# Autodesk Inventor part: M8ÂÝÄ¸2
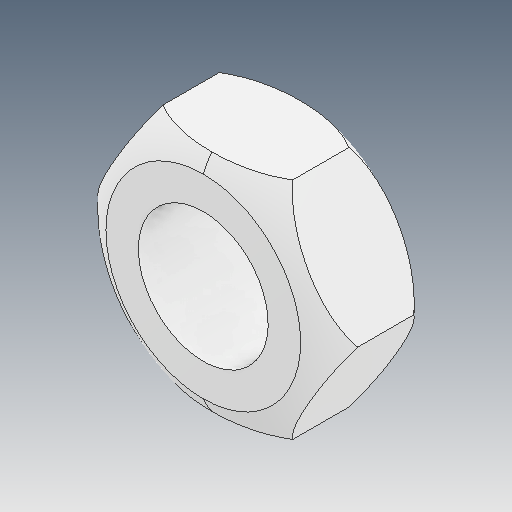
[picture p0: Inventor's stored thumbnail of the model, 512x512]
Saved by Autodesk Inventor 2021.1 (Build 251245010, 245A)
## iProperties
Created: 2021-05
Part Number: M8ÂÝÄ¸2
Material: Ogólny
Document SubType Name: Modeling
Designer: user
Density: 1 g/cm^3
Appearance: Domyślna
Author: user
Revision Number: ÈÎºÎ
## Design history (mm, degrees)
feature "ÊäÈë1"
node "Bryła1"
